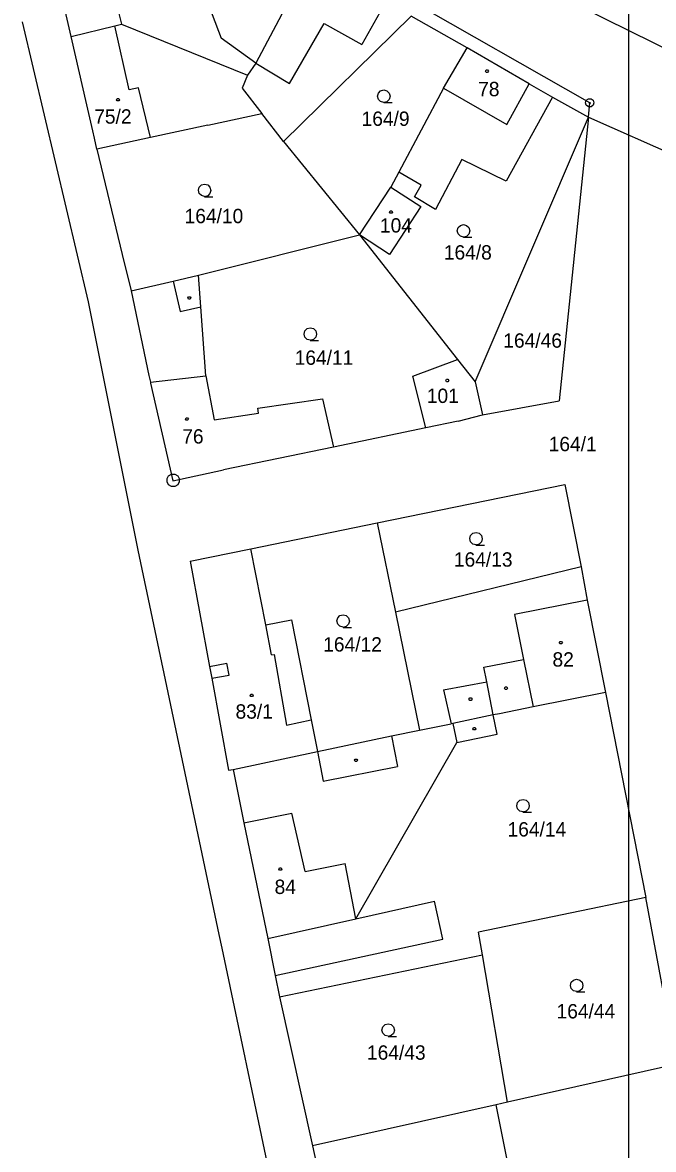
# Model space of a CAD drawing. Extents: x -780000 to -777378, y -1011169 to -1009297.
# Drawn here: x -779446.8 to -779372, y -1010258.1 to -1010124.6 of the extents above; entities that cross this region are included whole.
import ezdxf

# ---------------------------------------------------------------- set-up
doc = ezdxf.new("R2010")
doc.units = 0
for name, color, linetype in [('Default', 7, 'Continuous'), ('KLADY_ZMVM', 7, 'Continuous'), ('KN_HRANICE', 7, 'Continuous'), ('KN_KULTURY', 7, 'Continuous'), ('KN_PARCELY', 7, 'Continuous'), ('KN_SLUCKY', 7, 'Continuous')]:
    doc.layers.add(name, color=color, linetype=linetype)

# ---------------------------------------------------------------- blocks, each defined once
blk = doc.blocks.new('101')
at = {"layer": 'Default'}
blk.add_line((-0.05, 0), (0.05, 0), dxfattribs=at)
blk.add_lwpolyline([(0.19, 0.72), (0.53, 0.53), (0.72, 0.19), (0.72, -0.2), (0.53, -0.54), (0.19, -0.73), (-0.2, -0.73), (-0.54, -0.54), (-0.73, -0.2), (-0.73, 0.19), (-0.54, 0.53), (-0.2, 0.72), (0.19, 0.72)], dxfattribs=at)
blk = doc.blocks.new('304')
at = {"layer": 'Default'}
blk.add_lwpolyline([(0, 0), (-0.38, 0.1), (-0.65, 0.37), (-0.75, 0.74), (-0.65, 1.11), (-0.38, 1.38), (-0.01, 1.48), (0.36, 1.38), (0.63, 1.11), (0.73, 0.73), (0.63, 0.35), (0.36, 0.08), (-0.02, -0.02), (0.98, -0.02)], dxfattribs=at)
blk = doc.blocks.new('402')
at = {"layer": 'Default'}
blk.add_lwpolyline([(0.09, 0.15), (0.18, 0), (0.09, -0.15), (-0.09, -0.15), (-0.18, 0), (-0.09, 0.15), (0.09, 0.15)], dxfattribs=at)
blk = doc.blocks.new('105')
at = {"layer": 'Default'}
blk.add_line((-0.12, 0), (0.12, 0), dxfattribs=at)
blk.add_lwpolyline([(0.15, 0.48), (0.4, 0.3), (0.5, 0.01), (0.4, -0.28), (0.15, -0.46), (-0.16, -0.46), (-0.41, -0.28), (-0.51, 0.01), (-0.41, 0.3), (-0.16, 0.48), (0.15, 0.48)], dxfattribs=at)

msp = doc.modelspace()

# ---------------------------------------------------------------- linework, layer by layer
at = {"layer": 'KLADY_ZMVM'}
msp.add_lwpolyline([(-779375, -1010000), (-779375, -1010500), (-779108.78, -1010500)], dxfattribs=at)
at = {"layer": 'KN_HRANICE'}
for p, q in [((-779441.05, -1010126.3), (-779444.86, -1010109.68)), ((-779425.9, -1010119.46), (-779423.3, -1010126.5)), ((-779415.42, -1010122.39), (-779419.17, -1010129.45)), ((-779380.8, -1010122.72), (-779356.88, -1010134.5)), ((-779415.89, -1010138.74), (-779400.78, -1010123.88)), ((-779394.14, -1010127.63), (-779400.78, -1010123.88)), ((-779439.02, -1010157.72), (-779446.83, -1010124.56)), ((-779441.05, -1010126.3), (-779435.89, -1010125.03)), ((-779435.89, -1010125.03), (-779435.11, -1010124.84)), ((-779435.11, -1010124.84), (-779420.18, -1010130.88)), ((-779439.21, -1010134.38), (-779441.05, -1010126.3)), ((-779419.17, -1010129.45), (-779423.3, -1010126.5)), ((-779396.93, -1010132.43), (-779394.14, -1010127.63)), ((-779386.76, -1010131.89), (-779394.14, -1010127.63)), ((-779419.17, -1010129.45), (-779420.18, -1010130.88)), ((-779420.18, -1010130.88), (-779420.81, -1010132.43)), ((-779386.76, -1010131.89), (-779384.01, -1010133.48)), ((-779420.81, -1010132.43), (-779418.47, -1010135.43)), ((-779396.93, -1010132.43), (-779402.22, -1010142.37)), ((-779384.01, -1010133.48), (-779389.49, -1010143.43)), ((-779384.01, -1010133.48), (-779379.75, -1010135.84)), ((-779438.5, -1010137.45), (-779439.21, -1010134.38)), ((-779424.85, -1010136.8), (-779418.47, -1010135.43)), ((-779415.89, -1010138.74), (-779418.47, -1010135.43)), ((-779393.19, -1010167.19), (-779379.75, -1010135.84)), ((-779379.75, -1010135.84), (-779383.22, -1010169.47)), ((-779379.75, -1010135.84), (-779368.25, -1010140.93)), ((-779438.29, -1010138.35), (-779438.5, -1010137.45)), ((-779424.85, -1010136.8), (-779431.67, -1010138.26)), ((-779438.03, -1010139.63), (-779438.29, -1010138.35)), ((-779431.67, -1010138.26), (-779438.03, -1010139.63)), ((-779415.89, -1010138.74), (-779406.87, -1010149.81)), ((-779438.03, -1010139.63), (-779435, -1010152.13)), ((-779394.77, -1010140.85), (-779397.87, -1010146.79)), ((-779389.49, -1010143.43), (-779394.77, -1010140.85)), ((-779402.22, -1010142.37), (-779403.16, -1010144.15)), ((-779399.58, -1010143.89), (-779402.22, -1010142.37)), ((-779406.87, -1010149.81), (-779403.16, -1010144.15)), ((-779403.16, -1010144.15), (-779399.6, -1010146.43)), ((-779400.38, -1010145.27), (-779399.58, -1010143.89)), ((-779397.87, -1010146.79), (-779400.38, -1010145.27)), ((-779399.6, -1010146.43), (-779403.35, -1010152.12)), ((-779425.97, -1010154.58), (-779406.87, -1010149.81)), ((-779403.35, -1010152.12), (-779406.87, -1010149.81)), ((-779406.87, -1010149.81), (-779395.28, -1010164.54)), ((-779435, -1010152.13), (-779433.96, -1010156.43)), ((-779428.99, -1010155.28), (-779425.97, -1010154.58)), ((-779425.7, -1010158.32), (-779425.97, -1010154.58)), ((-779433.96, -1010156.43), (-779428.99, -1010155.28)), ((-779433.96, -1010156.43), (-779431.85, -1010166.47)), ((-779433.12, -1010187.16), (-779439.02, -1010157.72)), ((-779425.12, -1010166.48), (-779425.7, -1010158.32)), ((-779400.55, -1010166.52), (-779395.28, -1010164.54)), ((-779395.28, -1010164.54), (-779393.19, -1010167.19)), ((-779431.85, -1010166.47), (-779431.68, -1010167.23)), ((-779425.12, -1010166.48), (-779424.13, -1010171.7)), ((-779399.03, -1010172.67), (-779400.55, -1010166.52)), ((-779431.68, -1010167.23), (-779431.65, -1010167.35)), ((-779431.65, -1010167.35), (-779429.01, -1010178.94)), ((-779393.19, -1010167.19), (-779392.31, -1010171.12)), ((-779418.94, -1010170.34), (-779411.28, -1010169.22)), ((-779411.28, -1010169.22), (-779409.96, -1010174.94)), ((-779392.31, -1010171.12), (-779383.22, -1010169.47)), ((-779418.85, -1010170.93), (-779418.94, -1010170.34)), ((-779424.13, -1010171.7), (-779418.85, -1010170.93)), ((-779395.19, -1010171.87), (-779399.03, -1010172.67)), ((-779395.19, -1010171.87), (-779392.31, -1010171.12)), ((-779399.03, -1010172.67), (-779409.96, -1010174.94)), ((-779409.96, -1010174.94), (-779423, -1010177.65)), ((-779429.01, -1010178.94), (-779423, -1010177.65)), ((-779404.79, -1010183.9), (-779382.53, -1010179.37)), ((-779382.53, -1010179.37), (-779380.62, -1010189.12)), ((-779419.77, -1010186.97), (-779404.79, -1010183.9)), ((-779404.79, -1010183.9), (-779402.63, -1010194.49)), ((-779423.51, -1010232.67), (-779433.12, -1010187.16)), ((-779426.94, -1010188.44), (-779419.77, -1010186.97)), ((-779418, -1010195.98), (-779419.77, -1010186.97)), ((-779426.94, -1010188.44), (-779424.65, -1010200.94)), ((-779380.62, -1010189.12), (-779402.63, -1010194.49)), ((-779380.62, -1010189.12), (-779379.91, -1010193.08)), ((-779379.91, -1010193.08), (-779377.71, -1010203.99)), ((-779402.63, -1010194.49), (-779399.78, -1010208.48)), ((-779418, -1010195.98), (-779414.94, -1010195.39)), ((-779414.94, -1010195.39), (-779412.61, -1010207.26)), ((-779424.65, -1010200.94), (-779424.4, -1010202.32)), ((-779424.4, -1010202.32), (-779422.41, -1010213.23)), ((-779377.71, -1010203.99), (-779386.3, -1010205.71)), ((-779377.71, -1010203.99), (-779372.96, -1010228.31)), ((-779391.03, -1010206.67), (-779395.84, -1010207.67)), ((-779390.31, -1010206.52), (-779391.03, -1010206.67)), ((-779390.58, -1010208.93), (-779391.03, -1010206.67)), ((-779386.3, -1010205.71), (-779390.31, -1010206.52)), ((-779412.61, -1010207.26), (-779411.88, -1010211.01)), ((-779399.78, -1010208.48), (-779396.04, -1010207.71)), ((-779395.84, -1010207.67), (-779396.04, -1010207.71)), ((-779411.88, -1010211.01), (-779403.09, -1010209.16)), ((-779403.09, -1010209.16), (-779399.78, -1010208.48)), ((-779395.35, -1010209.92), (-779390.58, -1010208.93)), ((-779407.33, -1010230.83), (-779395.35, -1010209.92)), ((-779421.87, -1010213.12), (-779411.88, -1010211.01)), ((-779422.41, -1010213.23), (-779421.87, -1010213.12)), ((-779421.87, -1010213.12), (-779420.58, -1010219.44)), ((-779420.58, -1010219.44), (-779417.77, -1010233.17)), ((-779372.96, -1010228.31), (-779392.78, -1010232.41)), ((-779369.26, -1010248.05), (-779372.96, -1010228.31)), ((-779407.33, -1010230.83), (-779397.99, -1010228.74)), ((-779396.99, -1010233.24), (-779397.99, -1010228.74)), ((-779423.17, -1010234.28), (-779423.51, -1010232.67)), ((-779417.77, -1010233.17), (-779416.88, -1010237.53)), ((-779416.88, -1010237.53), (-779396.99, -1010233.24)), ((-779392.32, -1010235.07), (-779392.78, -1010232.41)), ((-779411.57, -1010289.24), (-779423.17, -1010234.28)), ((-779416.36, -1010240.08), (-779392.32, -1010235.07)), ((-779389.34, -1010252.55), (-779392.32, -1010235.07)), ((-779416.88, -1010237.53), (-779416.36, -1010240.08)), ((-779416.36, -1010240.08), (-779412.45, -1010257.73)), ((-779369.26, -1010248.05), (-779389.34, -1010252.55)), ((-779390.67, -1010252.85), (-779412.45, -1010257.73)), ((-779389.34, -1010252.55), (-779390.67, -1010252.85)), ((-779385.75, -1010277.38), (-779390.67, -1010252.85)), ((-779412.45, -1010257.73), (-779407.72, -1010279.08))]:
    msp.add_line(p, q, dxfattribs=at)
at = {"layer": 'KN_SLUCKY'}
for p, q in [((-779437.52, -1010114.87), (-779435.11, -1010124.84)), ((-779379.59, -1010134.15), (-779411.49, -1010115.98)), ((-779403.77, -1010122.18), (-779406.62, -1010127.23)), ((-779434.17, -1010132.62), (-779435.89, -1010125.03)), ((-779415.18, -1010131.88), (-779411.09, -1010124.77)), ((-779411.09, -1010124.77), (-779406.62, -1010127.23)), ((-779419.17, -1010129.45), (-779415.18, -1010131.88)), ((-779389.44, -1010136.7), (-779386.76, -1010131.89)), ((-779433.09, -1010132.38), (-779434.17, -1010132.62)), ((-779431.67, -1010138.26), (-779433.09, -1010132.38)), ((-779396.93, -1010132.43), (-779389.44, -1010136.7)), ((-779379.75, -1010135.84), (-779379.59, -1010134.15)), ((-779428.99, -1010155.28), (-779428.14, -1010158.86)), ((-779428.14, -1010158.86), (-779425.7, -1010158.32)), ((-779431.68, -1010167.23), (-779425.12, -1010166.48)), ((-779379.91, -1010193.08), (-779388.53, -1010194.78)), ((-779388.53, -1010194.78), (-779387.44, -1010200.1)), ((-779417.3, -1010199.54), (-779418, -1010195.98)), ((-779417.3, -1010199.54), (-779417.02, -1010199.49)), ((-779417.02, -1010199.49), (-779415.55, -1010207.86)), ((-779392.14, -1010201.01), (-779387.44, -1010200.1)), ((-779387.44, -1010200.1), (-779386.3, -1010205.71)), ((-779424.65, -1010200.94), (-779422.61, -1010200.55)), ((-779422.35, -1010201.94), (-779422.61, -1010200.55)), ((-779391.8, -1010202.74), (-779392.14, -1010201.01)), ((-779424.4, -1010202.32), (-779422.35, -1010201.94)), ((-779396.93, -1010203.68), (-779391.8, -1010202.74)), ((-779391.03, -1010206.67), (-779391.8, -1010202.74)), ((-779396.93, -1010203.68), (-779396.04, -1010207.71)), ((-779415.55, -1010207.86), (-779412.61, -1010207.26)), ((-779395.84, -1010207.67), (-779395.35, -1010209.92)), ((-779403.09, -1010209.16), (-779402.38, -1010212.79)), ((-779411.88, -1010211.01), (-779411.2, -1010214.51)), ((-779411.2, -1010214.51), (-779402.38, -1010212.79)), ((-779420.58, -1010219.44), (-779414.92, -1010218.29)), ((-779413.31, -1010225.22), (-779414.92, -1010218.29)), ((-779413.31, -1010225.22), (-779408.6, -1010224.25)), ((-779407.33, -1010230.83), (-779408.6, -1010224.25)), ((-779417.77, -1010233.17), (-779407.33, -1010230.83))]:
    msp.add_line(p, q, dxfattribs=at)

# ---------------------------------------------------------------- block references
at = {"layer": 'KN_KULTURY'}
for name, p in [('402', (-779391.79, -1010130.39)), ('304', (-779404, -1010134.11)), ('402', (-779435.51, -1010133.78)), ('304', (-779425.24, -1010145.25)), ('402', (-779403.16, -1010147.09)), ('304', (-779394.55, -1010150.05)), ('402', (-779427.06, -1010157.27)), ('304', (-779412.71, -1010162.28)), ('402', (-779396.49, -1010167.04)), ('402', (-779427.35, -1010171.61)), ('304', (-779393.06, -1010186.52)), ('304', (-779408.82, -1010196.27)), ('402', (-779383.02, -1010198.11)), ('402', (-779419.66, -1010204.35)), ('402', (-779389.53, -1010203.5)), ('402', (-779393.73, -1010204.81)), ('402', (-779393.27, -1010208.3)), ('402', (-779407.31, -1010212.04)), ('304', (-779387.49, -1010218.16)), ('402', (-779416.27, -1010224.92)), ('304', (-779381.14, -1010239.45)), ('304', (-779403.48, -1010244.74))]:
    msp.add_blockref(name, p, dxfattribs=at)
at = {"layer": 'KN_PARCELY'}
for name, p in [('105', (-779379.59, -1010134.15)), ('101', (-779428.97, -1010178.86))]:
    msp.add_blockref(name, p, dxfattribs=at)

# ---------------------------------------------------------------- texts
for s, p in [('78', (-779392.82, -1010133.37)), ('75/2', (-779438.33, -1010136.62)), ('164/9', (-779406.64, -1010136.88)), ('164/10', (-779427.62, -1010148.41)), ('104', (-779404.46, -1010149.52)), ('164/8', (-779396.89, -1010152.72)), ('164/46', (-779389.84, -1010163.16)), ('164/11', (-779414.57, -1010165.19)), ('101', (-779398.91, -1010169.71)), ('76', (-779427.9, -1010174.52)), ('164/1', (-779384.46, -1010175.42)), ('164/13', (-779395.7, -1010189.1)), ('164/12', (-779411.19, -1010199.16)), ('82', (-779384.01, -1010200.94)), ('83/1', (-779421.58, -1010207.11)), ('164/14', (-779389.34, -1010221.07)), ('84', (-779416.95, -1010227.88)), ('164/44', (-779383.53, -1010242.62)), ('164/43', (-779406, -1010247.51))]:
    msp.add_text(s, height=1.7, dxfattribs=at).set_placement(p)

doc.saveas('drawing.dxf')
